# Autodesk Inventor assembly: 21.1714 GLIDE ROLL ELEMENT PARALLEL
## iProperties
Created: 2007-05
Part Number: 21.1714 GLIDE ROLL ELEMENT PARALLEL
Document SubType Name: Assembly
Designer: Andy Moles
Author: Andy Moles
